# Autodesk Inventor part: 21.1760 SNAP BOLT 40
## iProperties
Created: 2007-01
Part Number: 21.1760 SNAP BOLT 40
Document SubType Name: Modeling
Designer: Andy Moles
Material: Steel
Density: 7.85 g/cm^3
Author: Andy Moles
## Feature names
1. Extrusion1
2. Extrusion2
3. Chamfer1
4. Chamfer2
